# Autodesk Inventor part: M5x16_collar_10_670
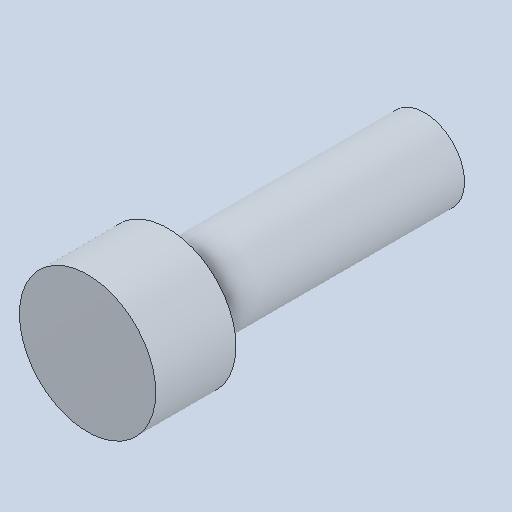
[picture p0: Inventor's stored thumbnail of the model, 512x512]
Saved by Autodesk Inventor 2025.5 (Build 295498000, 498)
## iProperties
Created: 2026-10
Part Number: M5x16_collar_10_670
Material: Genérico
Document SubType Name: Modeling
Designer: Luis M
Density: 1 g/cm^3
Appearance: Valor por defecto
Author: Luis M
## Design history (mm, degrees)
feature "Base1"
node "Sólido1"
